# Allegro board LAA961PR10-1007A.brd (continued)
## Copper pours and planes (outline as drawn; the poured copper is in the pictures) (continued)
GND on IN4 (solid shape): 82.12,140 82.29,139.92 82.37,139.75 82.37,134.51 81.88,133.67 82.62,133.05 85.08,133.05 85.08,131.04 81.08,127.04 71.49,127.04 71.16,127.37 71.16,128.8 72.92,128.8 73.65,129.43 73.15,130.26 73.15,137.25 73.37,137.78 73.9,138 74.03,138 79,138 79.66,138.18 80.12,138.69 80.57,139.58 80.68,139.74 81.02,139.96 81.24,140
GND on IN4 (solid shape): 263.02,120.2 246.03,120.2 245.4,120.11 244.82,119.85 241.26,117.59 240.52,117.12 240.33,117.03 240.12,117 235.7,117 234.81,116.64 234.45,115.75 234.45,114.94 234.3,114.49 233.91,114.22 233.78,114.17 233.67,114.1 233.58,114.09 233.51,114.15 233.44,114.33 233.36,114.5 233.55,114.63 233.77,114.71 233.89,114.8 233.94,114.94 233.94,115.75 234.45,117 235.7,117.51 240.12,117.51 240.19,117.52 240.25,117.55 241.1,118.09 244.54,120.28 245.25,120.6 246.03,120.71 263.02,120.71
GND on IN4 (solid shape): outline of 189 points within 234.07,127.91 244.37,138.6
GND on IN4 (solid shape): 266.35,139.25 268,137.6 269.65,139.25 269.65,140 270.18,140 270.57,139.88 270.85,139.58 270.86,139.56 271.43,138.41 271.71,138.11 272.11,138 272.3,138 272.47,137.92 272.55,137.75 272.55,135.45 272.91,134.56 273.8,134.2 282.4,134.2 283.29,134.56 283.65,135.45 283.65,139.25 283.87,139.78 284.4,140 285.43,140 285.6,139.92 285.68,139.75 285.68,131.73 285.3,131.35 285.3,129.18 285.14,129.02 284.4,129.02 281.06,132.36 275.12,132.36 273.8,133.69 272.83,133.98 272.18,134.75 271.25,135.68 260.73,135.68 258.08,133.03 252.66,133.03 252.73,133.21 252.75,133.39 252.75,134.65 252.75,135.82 253.05,136.06 253.15,136.42 253.15,137.47 253.51,137.65 253.65,138.02 253.65,138.35 253.73,138.52 253.9,138.6 254.86,138.6 259.6,138.6 259.6,140.75 259.68,140.92 259.85,141 266.35,141
GND on IN4 (solid shape): 58.4,138.6 58.93,138.38 59.15,137.85 59.15,130.26 58.66,129.42 59.4,128.8 60.51,128.8 61.14,128.8 61.14,128.29 60.54,128.29 58.75,126.49 58.36,126.42 58.28,126.03 54.4,122.14 54.4,120.68 65.44,105.43 66.26,86.61 66.5,86.61 68.66,84.45 66.5,82.29 64.84,82.29 52.78,67.46 34.5,61.89 6.2,61.89 5.68,61.67 5.46,61.15 5.46,54.27 5.29,53.41 4.8,52.67 4.18,52.05 4.02,51.81 3.96,51.53 3.96,45.25 3.45,44 2.2,43.49 1,43.49 0.83,43.42 0.76,43.25 0.76,16.3 0.25,16.3 0.25,43.25 0.47,43.78 1,44 2.2,44 3.09,44.36 3.45,45.25 3.45,51.53 3.55,52.01 3.82,52.41 4.44,53.03 4.82,53.6 4.95,54.27 4.95,61.15 5.32,62.03 6.2,62.4 34.5,62.4 52.62,67.97 64.48,82.76 64.5,82.8 66.5,82.8 68.15,84.45 66.5,86.1 65.73,86.1 65.65,86.14 65.64,86.23 64.09,107.48 49.64,123.13 48.19,124.51 47.65,126.44 47.65,138.35 47.73,138.52 47.9,138.6 58.09,138.6
GND on IN4 (solid shape): outline of 198 points within 0.25,0.25 236.25,109.92
GND on IN4 (solid shape): outline of 1199 points within 95.84,124.76 224.02,140.6
GND on IN4 (solid shape): outline of 2707 points within 56.97,25.32 93.25,34.58
GND on GND1: outline of 314 points within 0.26,0.25 287.14,141 ; 1 cut-out
GND on GND2: outline of 315 points within 0.26,0.25 287.14,141 ; 1 cut-out
GND on VCC: outline of 255 points within 0.25,15.98 190.45,140.6
GND on VCC: 135.05,19.61 132.38,22.28 55.69,22.28 55.69,33.35 57.26,34.92 84.25,34.92 86.62,37.29 86.62,64.97 90.43,68.78 90.43,72.78 93.52,75.87 101.43,75.87 102.26,75.05 103.49,75.05 104.06,75.62 124.21,75.62 124.21,75.58 124.8,74.98 126.71,74.98 127.41,74.29 127.72,74.29 128.15,73.86 128.15,73.81 128.13,73.74 128.15,73.71 128.15,69.16 129.12,68.19 129.95,68.19 131.51,66.62 131.51,63.83 134.71,60.63 137.16,60.63 137.4,60.55 137.65,60.63 143.92,60.63 145.19,59.36 147.79,59.36 148.36,58.79 172.55,58.79 184.16,47.18 185.88,47.18 195.65,37.41 195.65,23.02 194.78,22.15 172.05,22.15 169.51,19.61
GND on GND3: outline of 313 points within 0.26,0.25 287.14,141
GNDA on TOP (solid shape): 217.34,67.23 217.34,67.2 217.4,66.89 217.68,66.75 217.72,66.74 217.73,66.7 217.73,64.54 217.59,64.41 217.39,64.41 217.39,65.3 216.17,66.52 216.17,67.35 217.22,67.35
GNDA on TOP (solid shape): 211.42,67.36 211.83,67.36 214.19,67.36 214.9,66.65 214.9,66 216.12,64.78 216.12,63.96 215.43,63.96 215.41,63.94 214.91,63.94 214.87,63.9 214.63,63.9 214.62,63.91 214.1,63.91 214.07,63.88 214,63.88 213.97,63.91 213.39,63.91 213.3,64 211.34,64 211.29,64.05 210.81,64.05 210.44,63.68 209.87,63.68 209.56,63.37 209.16,63.37 208.99,63.55 208.99,64.24 208.69,64.53 208.69,65.31 208.76,65.37 210.77,65.37 211.06,65.67 212.07,65.67 212.19,65.79 212.19,66.67 212.03,66.83 211.34,66.83 210.44,67.73 210.44,67.97 210.5,68.04 210.75,68.04
GNDA on IN2 (solid shape): outline of 781 points within 206.05,62.96 221.71,76.17
GNDA on GND1, GND2: 207.44,63.05 206.42,64.06 206.1,64.06 205.87,64.29 205.87,66.75 207.05,67.94 208.77,67.94 209.11,68.27 209.11,72.87 208.2,73.78 207.97,73.78 207.97,74.56 208.13,74.73 209.72,74.73 210.19,75.2 210.19,77.04 211.12,77.97 219.67,77.97 219.9,77.74 219.9,75.64 221.81,73.74 221.81,69.76 221.58,69.52 218.97,69.52 217.68,68.23 217.68,64.8 216.88,64 211.03,64 210.08,63.05
GNDA_CHG on TOP (solid shape): 36.07,43.4 39.18,43.4 39.37,43.21 40.52,43.21 40.67,43.06 40.67,42.36 40.38,42.36 40.2,42.18 40.2,41.2 40.04,41.05 40.04,40.52 40.05,40.52 40.24,40.33 40.24,40.31 40.46,40.31 40.59,40.29 40.73,40.31 40.81,40.31 40.95,40.17 40.95,39.41 40.82,39.28 38.34,39.28 37.71,38.65 36.25,38.65 36.1,38.8 36.1,42.26 35.75,42.6 34.72,42.6 34.41,42.92 34.41,43.35 34.94,43.35 34.94,43.83 34.39,43.83 34.39,44.21 34.44,44.26 35.21,44.26
VDD_1.35V on TOP (solid shape): 74.78,20.86 74.78,20.42 74.79,20.41 74.79,19.37 74.54,19.12 73.88,19.12 73.69,19.31 73.69,20.7 74.01,21.02 74.62,21.02
VDD_1.35V on BOTTOM (solid shape): 74.7,20.77 74.7,20.46 74.84,20.32 75.25,20.32 75.42,20.16 75.42,19.42 75.47,19.37 76.56,19.37 76.66,19.27 76.66,18.24 76.58,18.16 74.63,18.16 74.17,18.62 74.17,20.81 74.28,20.92 74.55,20.92
+BL_PWR_SRC on TOP (solid shape): outline of 129 points within 92.44,110.79 99.39,116.73
+BL_PWR_SRC on BOTTOM (solid shape): 98.59,116.78 98.59,115.6 98.99,115.21 99.24,115.21 99.37,115.08 99.37,113.82 99.17,113.62 97.67,113.62 97.51,113.77 97.51,115.13 97.34,115.31 97.34,116.77 97.42,116.86 98.52,116.86
+DC_IN on TOP (solid shape): 69.41,101.4 71.14,101.4 71.24,101.29 71.24,100.57 70.74,100.07 70.74,98.42 70.04,97.72 67.85,97.72 67.69,97.87 67.69,101.59 67.76,101.66 69.15,101.66
+DC_IN on BOTTOM (solid shape): 48.28,41.96 50.32,41.96 50.64,41.65 50.64,40.01 50.14,39.51 48.86,39.51 48.85,39.5 47.98,39.5 47.74,39.74 47.74,41.71 48.01,41.98 48.26,41.98
+DC_IN on BOTTOM (solid shape): outline of 1580 points within 44.06,58.09 75.67,102.03
+DC_IN on IN3 (solid shape): outline of 265 points within 46.17,38.11 51.84,65.54
+DC_IN_SS on TOP (solid shape): 46.36,41.01 46.36,39.11 45.94,38.69 44.14,38.69 43.68,39.15 43.6,39.28 43.47,39.36 43.45,39.39 43.45,41.37 43.56,41.48 45.89,41.48
+DC_IN_SS on BOTTOM (solid shape): outline of 87 points within 43.09,38.73 47.49,47.49
+DCIN on TOP (solid shape): 44.11,45.61 44.11,43.87 43.65,43.41 39.51,43.41 39.31,43.62 39.31,44.1 39.5,44.29 40.07,44.29 40.31,44.3 40.49,44.47 40.5,44.5 40.52,44.54 42.46,44.54 42.85,44.92 42.85,45.54 43.04,45.74 43.98,45.74
+DCIN on BOTTOM (solid shape): 40.69,44.05 40.69,43.56 40.6,43.48 39.26,43.48 39.02,43.23 39.02,42.74 38.98,42.7 38.85,42.7 38.81,42.74 38.81,43.53 39.49,44.2 40.54,44.2
+DCIN_JACK on TOP (solid shape): 82.37,116.92 82.37,116.13 81.75,115.5 81.51,115.5 81.41,115.4 81.4,115.4 81.2,115.3 81.1,115.11 81.1,115.09 80.82,114.81 80.82,113.42 80.66,113.26 79.66,113.26 79.54,113.13 79.54,112.27 79.33,112.06 78.81,112.06 78.54,112.33 78.54,115.09 79.26,115.81 79.26,116.86 79.56,117.15 82.15,117.15
+DCIN_JACK on BOTTOM (solid shape): 82.8,114.32 82.8,111.94 82.42,111.56 74.23,111.56 72.3,109.63 72.26,109.63 72.21,109.62 72.16,109.61 72.12,109.58 72.07,109.55 72.04,109.52 72,109.48 71.98,109.44 71.95,109.38 71.94,109.33 71.94,109.27 71.94,109.22 71.95,109.19 71.95,104.58 71.65,104.28 67.8,104.28 67.44,104.64 67.44,108.16 69.03,108.16 69.03,108.1 69.03,108.05 69.05,108 69.07,107.95 69.1,107.91 69.14,107.87 69.18,107.84 69.23,107.81 69.28,107.79 69.33,107.78 69.38,107.77 69.44,107.78 69.49,107.79 69.54,107.81 69.58,107.84 69.63,107.87 69.66,107.91 69.69,107.95 69.71,108 69.73,108.05 69.74,108.1 69.74,108.16 69.73,108.21 69.71,108.26 69.69,108.31 69.66,108.35 69.63,108.39 69.58,108.43 69.54,108.45 69.49,108.47 69.44,108.48 69.38,108.49 69.33,108.48 69.28,108.47 69.23,108.45 69.18,108.43 69.14,108.39 69.1,108.35 69.07,108.31 69.05,108.26 69.03,108.21 69.03,108.16 67.44,108.16 67.44,113.27 68.77,114.61 82.52,114.61
+DOCK_PWR_BAR on TOP (solid shape): 202.5,24.83 202.5,20.9 202.17,20.58 200,20.58 199.89,20.46 199.89,16.84 199.81,16.77 198.07,16.77 197.93,16.91 197.93,21.11 198.47,21.64 199.49,21.64 199.74,21.89 199.74,25.02 202.3,25.02
+DOCK_PWR_BAR on TOP (solid shape): outline of 159 points within 139.61,130.7 147.54,138.92
+DOCK_PWR_BAR on BOTTOM (solid shape): 202.31,24.78 202.31,17.66 201.31,16.65 201.31,15.78 201.26,15.73 199.44,15.73 199.16,16.01 199.16,21.52 199.66,22.01 199.66,24.86 199.82,25.02 202.07,25.02
+DOCK_PWR_BAR on IN4 (solid shape): outline of 2551 points within 221.8,34.7 233.67,97.17
+DOCK_PWR_BAR on VCC: outline of 102 points within 130.75,17.45 233.67,139.58
+LCDVDD on TOP (solid shape): 78.35,124.93 78.35,122.8 78.06,122.51 75.75,122.51 75.59,122.66 75.59,124.25 76.08,124.73 76.08,125.07 76.24,125.24 78.04,125.24
+LCDVDD on BOTTOM (solid shape): 92.13,116.78 92.13,115.52 92.65,115 93.23,115 93.43,114.81 93.43,114.07 93.3,113.94 92.36,113.94 91.82,114.48 90.86,114.48 90.67,114.67 90.67,115.1 90.97,115.41 90.99,115.41 91.15,115.48 91.22,115.64 91.22,115.66 91.33,115.76 91.33,116.75 91.46,116.88 92.03,116.88
+LCDVDD on IN4 (solid shape): 78.78,125.25 78.78,123.14 78.54,122.9 76.61,122.9 76.27,123.24 76.27,125.2 76.42,125.35 78.68,125.35
+LCDVDD on IN4 (solid shape): 92.48,116.6 92.48,114.93 92.29,114.75 90.82,114.75 90.57,115 90.57,117.05 90.77,117.25 91.82,117.25
+PBATT on TOP (solid shape): 15.39,52.56 15.39,46.38 15.18,46.17 14.21,46.17 13.64,46.74 13.53,47.3 13.03,48.45 12.39,49.3 11.79,49.83 11.03,50.26 10.02,50.66 10.02,52.89 10.43,53.29 14.66,53.29
+PBATT on BOTTOM (solid shape): 13.9,51.07 14.89,51.07 15.31,50.65 15.31,46.19 15.15,46.04 14.28,46.04 13.66,46.66 13.6,46.69 13.52,47.35 13.13,48.26 12.72,48.97 11.95,49.74 11.78,49.84 11.22,50.17 10.73,50.37 10.27,50.54 9.49,50.7 8.98,50.7 8.69,50.99 8.69,52.42 8.97,52.7 12.27,52.7
+PBATT on BOTTOM (solid shape): outline of 264 points within 159.88,6.53 195.01,21.67
+PBATT on IN3 (solid shape): outline of 245 points within 13.32,39.49 32.13,48.61
+PBATT on VCC: 61.58,1.42 61.12,1.58 60.87,2 60.37,4.32 59.58,5.62 58.15,6.12 5.2,6.12 4.68,6.33 4.47,6.85 4.47,9.85 3.81,11.46 2.2,12.12 1.27,12.12 1.27,42.98 2.2,42.98 3.81,43.64 4.47,45.25 4.47,51.53 4.49,51.62 4.54,51.69 5.16,52.31 5.76,53.21 5.97,54.27 5.97,61.15 6.04,61.31 6.2,61.38 16.27,61.38 16.27,46.03 15.26,45.02 15.26,16.62 15.24,16.61 15.24,16.33 18.12,13.45 85.43,13.45 86.26,12.63 163.49,12.63 164.26,13.39 187.16,13.39 187.84,12.71 187.84,6.12 183.11,6.12 183.11,6.12 180.56,6.12 179.7,5.95 178.96,5.46 178.76,5.26 147.8,5.26 147.66,5.33 147.52,5.38 145.84,5.99 145.47,6.09 145.08,6.12 78.57,6.12 77.14,5.62 76.35,4.32 75.85,2 75.6,1.58 75.14,1.42 74.54,1.42 74.37,1.44 74.21,1.5 68.36,2.92 62.51,1.5 62.35,1.44 62.18,1.42
+PCH_VCC1P05 on IN2 (solid shape): outline of 243 points within 127.45,85.02 129.1,89.53
+PCH_VCCDSW on TOP (solid shape): outline of 569 points within 125.76,67.26 128.13,75.44
+PCH_VCCDSW3_3 on TOP (solid shape): outline of 85 points within 132.35,73.78 138.72,75.64
+PCH_VCCDSW3_3 on IN1 (solid shape): 157.62,75.76 157.62,74.59 157.46,74.43 156.43,74.43 156.12,74.73 156.12,76.06 156.32,76.25 157.13,76.25
+PWR_SRC on TOP (solid shape): 92.29,112.76 92.4,112.51 92.64,112.41 92.68,112.38 92.98,112.38 93.15,112.21 93.15,110.9 92.9,110.65 90.35,110.65 89.99,111.02 89.99,112.64 90.37,113.03 92.03,113.03
+PWR_SRC on TOP (solid shape): 28.96,58.56 28.96,56.94 28.18,56.16 28.18,50.23 27.33,49.38 17.67,49.38 17.2,49.85 17.2,51.08 17.22,51.21 17.2,51.34 17.2,52.24 17.24,52.28 25.62,52.28 25.86,52.52 25.86,55.3 25.25,55.91 25.25,58.35 25.77,58.87 28.65,58.87
+PWR_SRC on TOP (solid shape): 92.48,13.14 92.48,12.61 92.51,12.59 93.17,12.59 93.32,12.44 93.32,11.03 93.18,10.89 93.18,9.33 93.06,9.2 87,9.2 86.9,9.3 86.9,12.39 87.11,12.6 91.39,12.6 91.43,12.64 91.43,13.12 91.46,13.15 91.66,13.15 91.68,13.12 91.68,12.64 91.72,12.6 92.2,12.6 92.23,12.63 92.23,13.14 92.26,13.16 92.46,13.16
+PWR_SRC on BOTTOM (solid shape): 78.9,102.14 79.61,102.14 79.61,102.67 80.1,102.67 80.1,102.67 80.1,102.16 80.1,102.16 80.1,102.12 80.81,102.12 81.11,101.82 81.11,98.53 80.77,98.2 77.47,98.2 76.96,98.71 76.96,101.87 77.22,102.13 78.42,102.13 78.43,102.15 78.43,102.67 78.9,102.67
+PWR_SRC on BOTTOM (solid shape): 197.25,69.59 197.25,67.24 197.04,67.03 195.96,67.03 195.81,67.19 195.81,68.14 195.77,68.18 195.29,68.18 195.27,68.2 195.27,68.41 195.29,68.43 195.8,68.43 195.82,68.46 195.82,68.94 195.8,68.96 195.29,68.96 195.27,68.99 195.27,69.22 195.28,69.23 195.8,69.23 195.82,69.26 195.82,69.68 195.85,69.7 197.13,69.7
+PWR_SRC on BOTTOM (solid shape): 37.84,17.05 37.95,17.05 37.96,17.03 37.96,16.36 37.98,16.35 38.5,16.35 38.51,16.34 38.51,15.94 38.47,15.9 37.99,15.9 37.96,15.88 37.96,15.19 37.99,15.17 38.5,15.17 38.51,15.15 38.51,14.71 38.5,14.7 37.98,14.7 37.96,14.68 37.96,12.16 37.63,11.83 33.61,11.83 33.31,12.12 33.31,16.64 33.73,17.06 37.82,17.06
+PWR_SRC on BOTTOM (solid shape): outline of 85 points within 15.57,43.66 25.09,54.82
+PWR_SRC on IN2 (solid shape): outline of 3861 points within 1.81,6.57 94.57,100.6
+PWR_SRC on IN3 (solid shape): 201.04,29.04 201.04,27.02 200.7,26.68 199.51,26.68 199.07,27.12 199.07,28.3 198.48,28.89 198.26,28.89 198.11,29.04 198.11,29.77 198.32,29.98 200.1,29.98
+PWR_SRC on IN3 (solid shape): 95.62,12.68 95.62,10.18 95.39,9.96 87.16,9.96 86.96,10.16 86.96,10.39 93.25,10.39 93.25,10.34 93.25,10.29 93.27,10.24 93.29,10.19 93.32,10.14 93.36,10.1 93.4,10.07 93.45,10.04 93.5,10.03 93.55,10.01 93.6,10.01 93.65,10.01 93.71,10.03 93.76,10.04 93.8,10.07 93.84,10.1 93.88,10.14 93.91,10.19 93.93,10.24 93.95,10.29 93.96,10.34 93.96,10.39 93.95,10.45 93.93,10.5 93.91,10.54 93.88,10.59 93.84,10.63 93.8,10.66 93.76,10.69 93.71,10.71 93.65,10.72 93.6,10.72 93.55,10.72 93.5,10.71 93.45,10.69 93.4,10.66 93.36,10.63 93.32,10.59 93.29,10.54 93.27,10.5 93.25,10.45 93.25,10.39 86.96,10.39 86.96,12.49 87.23,12.76 95.53,12.76
+PWR_SRC on IN4 (solid shape): 197.64,69.49 197.64,65.32 197.37,65.04 195.52,65.04 195.34,65.22 195.34,69.79 195.42,69.86 197.26,69.86
+PWR_SRC on IN4 (solid shape): 200.15,31.74 200.15,29.27 199.78,28.9 198.08,28.9 197.66,29.32 197.66,31.83 197.82,31.99 199.9,31.99
+PWR_SRC on IN4 (solid shape): 80.18,104.39 80.18,98.46 79.86,98.14 77.51,98.14 77.34,98.31 77.34,104.27 77.69,104.63 79.94,104.63
+PWR_SRC on IN4 (solid shape): 92.32,112.91 92.32,112.89 92.29,112.77 92.32,112.64 92.32,108.55 92.04,108.28 90.01,108.28 89.85,108.43 89.85,109.47 88.91,110.4 88.91,112.43 89.54,113.05 92.18,113.05
+PWR_SRC_AC on TOP (solid shape): outline of 356 points within 200.14,11.75 215.27,21.59
+PWR_SRC_AC on BOTTOM (solid shape): 207.26,22.08 207.29,22.07 208.06,22.07 208.08,22.08 211.19,22.08 211.67,21.59 211.67,16.69 211.43,16.45 206.87,16.45 206.8,16.53 206.8,17.97 206.5,18.27 204.68,18.27 204.43,18.51 204.43,21.58 204.93,22.08
+PWR_SRC_AC on BOTTOM (solid shape): 50.64,55.6 50.64,52.06 49.94,51.36 48.85,51.36 48.85,52.73 48.72,53 48.44,53.09 48.16,53 48.03,52.73 48.03,51.36 47.4,51.36 46.89,50.85 46.89,49.39 46.6,49.1 43.92,49.1 43.77,49.25 43.77,54.89 45.04,56.16 50.08,56.16
+PWR_SRC_AC on IN1 (solid shape): 211.13,19.47 211.13,19.04 211.04,18.95 211.04,16.54 210.87,16.37 208.99,16.37 208.73,16.64 208.73,19.26 209.02,19.55 211.05,19.55
+PWR_SRC_AC on IN1 (solid shape): outline of 677 points within 1.34,7.01 19.33,61.08
+PWR_SRC_AC on IN3 (solid shape): outline of 677 points within 6.32,52.31 45.72,61.04
+PWR_SRC_AC on IN4 (solid shape): outline of 3055 points within 1.81,4.87 211.11,61.04
+RTC_CELL on TOP (solid shape): 215.32,86.71 215.83,86.71 215.98,86.56 215.98,86.16 215.76,85.94 215.7,85.91 214.83,85.91 214.69,86.05 214.69,86.62 214.78,86.72 215.32,86.72
+SDC_IN on BOTTOM (solid shape): 48.03,48.97 48.16,48.71 48.44,48.62 48.72,48.71 48.85,48.97 48.85,50.35 49.28,50.35 49.37,50.26 49.37,48.16 50.38,47.15 50.38,44.03 50.24,43.89 46.54,43.89 46.28,44.15 46.28,47.57 47.41,48.7 47.41,50.31 47.45,50.35 48.03,50.35
+SIM_PWR on TOP (solid shape): 70.71,18.28 70.71,15.96 70.59,15.84 70.31,15.84 70.16,15.99 70.16,17.03 69.21,17.98 69.21,18.61 69.25,18.65 70.34,18.65
+SIM_PWR on BOTTOM (solid shape): 213.11,66.44 213.11,64.77 213.27,64.61 213.27,62.4 213.2,62.32 212.83,62.32 212.71,62.44 212.71,63.15 212.73,63.17 212.73,63.68 212.74,63.69 212.74,64.58 212.79,64.63 212.79,64.72 212.81,64.74 212.81,65.74 212.8,65.79 212.79,65.85 212.79,66.42 212.91,66.54 213.01,66.54
+SIM_PWR on IN3 (solid shape): 70.69,18.2 70.69,15.8 70.53,15.64 69.71,15.64 69.47,15.88 69.47,18.32 69.6,18.44 70.45,18.44
+SIM_PWR on IN3 (solid shape): 220.73,43.49 220.73,42.82 219.92,42 219.48,42 219.13,42.36 219.13,43.07 219.85,43.79 220.42,43.79
+SIM_PWR on IN4 (solid shape): 214.11,63.01 214.11,62.41 213.76,62.06 213.26,62.06 212.74,62.57 212.74,63.3 212.82,63.38 213.74,63.38
+SIM_PWR on IN4 (solid shape): 220.69,43.51 220.69,43.17 220.23,42.71 220.06,42.71 219.26,43.51 219.26,43.87 219.65,44.26 219.94,44.26
+USB_RIGHT_PWR on BOTTOM (solid shape): 234.48,126.69 240,126.69 241.26,125.43 241.68,125.43 241.68,125.42 242.12,125.42 242.3,125.25 242.3,123.96 243.04,123.22 245.24,123.22 245.54,123.52 246.83,123.52 246.98,123.37 246.98,121.3 246.91,121.22 242.96,121.22 241.48,122.7 241.48,123.05 241,123.54 241,123.9 239.49,125.4 233.05,125.4 231.9,126.55 231.9,127.44 232.16,127.69 233.48,127.69
+V_DDR_REF on BOTTOM (solid shape): 77.05,15.92 77.05,14.61 76.95,14.51 75.77,14.51 75.2,13.94 74.54,13.94 74.49,13.99 74.49,14.43 74.96,14.9 75.28,14.9 75.28,14.89 76.73,14.89 76.85,15.01 76.85,15.9 76.9,15.95 77.02,15.95
+VCHGR on TOP (solid shape): 18.14,60.53 18.14,54.33 18.09,54.28 12.18,54.28 11.33,55.13 11.33,60.62 11.56,60.85 17.82,60.85
+VCHGR on BOTTOM (solid shape): 18.29,58.72 18.29,52.49 17.41,51.62 17.12,51.62 16.93,51.81 16.93,53.41 16.82,53.52 16.32,53.52 16.09,53.29 16.09,51.96 15.86,51.72 14.28,51.72 12.83,53.18 6.89,53.18 6.45,53.61 6.45,57.76 7.51,58.82 11.28,58.82 11.93,59.46 17.54,59.46
+VDISPLAY_VCC on TOP (solid shape): 252.29,126.72 252.29,125.67 251.48,124.86 250.66,124.86 250.66,124.86 250.64,124.84 250.34,125.14 250.34,125.42 250.65,125.73 250.65,125.81 251.2,126.36 251.2,126.58 251.2,126.63 251.37,126.8 252.21,126.8
+VDISPLAY_VCC on BOTTOM (solid shape): 251.48,129.11 251.48,127.56 252.35,126.69 252.35,125.92 252.12,125.7 251.42,125.7 251.39,125.73 251.39,126.34 251.26,126.46 251.26,126.81 251.04,127.03 251.04,129.11 251.13,129.2 251.39,129.2
+VHDMI_VCC on BOTTOM (solid shape): 96.03,131.02 96.03,129.34 96.86,128.51 97.62,128.51 97.75,128.38 97.75,127.39 97.52,127.16 96.96,127.16 96.62,127.5 96.18,127.5 96.04,127.36 94.84,127.36 94.66,127.54 94.07,127.54 93.75,127.22 93.75,126.86 93.45,126.56 91.57,126.56 91.43,126.7 91.43,127.32 91.57,127.46 92.84,127.46 92.85,127.47 93.01,127.47 93.12,127.57 93.12,127.74 93.47,128.09 94.08,128.71 94.08,131.12 94.26,131.3 95.75,131.3
+VLDOIN_1.35V on TOP (solid shape): 82.07,17.19 82.07,16.96 82.04,16.93 81.54,16.93 81.51,16.91 81.51,16.46 81.52,16.45 82.07,16.45 82.08,16.44 82.08,15.74 81.98,15.64 79.63,15.64 79.42,15.85 79.42,16.45 79.89,16.92 81.14,16.92 81.46,17.24 82.02,17.24
+VLDOIN_1.35V on BOTTOM (solid shape): 79.94,16.36 80.15,16.36 80.27,16.25 80.27,15.84 80.2,15.78 79.9,15.78 79.52,16.16 79.52,16.36 79.36,16.51 78.49,16.51 78.44,16.56 78.44,16.7 78.5,16.77 79.53,16.77
-DCIN_JACK on TOP (solid shape): outline of 91 points within 72.27,104.68 82.8,110.74
-DCIN_JACK on BOTTOM (solid shape): outline of 109 points within 72.27,104.2 82.8,110.59
BOOT_1.35V on BOTTOM (solid shape): 80.11,16.95 81.97,16.95 82.12,16.79 82.12,16.11 82.02,16.01 80.52,16.01 80.41,16.12 80.41,16.59 80.33,16.67 79.92,16.67 79.63,16.96 78.53,16.96 78.45,17.03 78.45,17.1 78.51,17.16 79.9,17.16
BOOT_1.35V_C on BOTTOM (solid shape): 83.05,18.15 83.05,16.03 82.98,15.97 82.41,15.97 82.35,16.03 82.35,18.16 82.39,18.2 83,18.2
BQ24770_REGN on BOTTOM (solid shape): 36.27,46.21 36.27,45.34 36.78,44.84 37.21,44.84 37.51,44.54 37.51,44.46 37.54,44.39 37.54,43.97 37.42,43.84 37.42,42.73 37.38,42.69 37.28,42.69 37.21,42.75 37.21,43.84 36.03,45.03 35.57,45.03 35.36,45.24 35.36,46.21 35.49,46.33 36.15,46.33
BST_3V on TOP (solid shape): 44.12,24.77 45.72,24.77 45.75,24.74 45.75,24.6 45.72,24.58 43.39,24.58 43.27,24.46 42.69,24.46 42.61,24.54 42.61,25.3 42.67,25.36 43.53,25.36
BST_3V_C on TOP (solid shape): 41.94,26.6 41.94,24.51 41.8,24.37 41.25,24.37 41.11,24.51 41.11,25.31 40.67,25.76 40.67,26.62 40.76,26.71 41.82,26.71
BST_5V on TOP (solid shape): 51.32,25.19 51.32,24.31 51.31,24.3 50.59,24.3 50.31,24.58 47.82,24.58 47.74,24.65 47.74,24.68 47.83,24.77 48.64,24.77 48.71,24.83 50.1,24.83 50.49,25.21 51.3,25.21
BST_5V_C on TOP (solid shape): 52.8,26.38 52.8,24.39 52.69,24.29 52.14,24.29 52.06,24.36 52.06,26.43 52.11,26.48 52.69,26.48
BST_+V1.05SP on TOP (solid shape): 192.38,67.64 192.38,66.42 192.17,66.21 191.2,66.21 191.02,66.39 191.02,67.64 191.18,67.8 192.23,67.8
BST_+V1.05SP_C on TOP (solid shape): 192.13,69.19 192.13,68.06 192,67.94 189.99,67.94 189.69,68.24 189.69,69.12 189.83,69.26 192.06,69.26
CHAGER_SRC on TOP (solid shape): outline of 89 points within 31.98,46.07 42.31,56.44
CHAGER_SRC on BOTTOM (solid shape): 43.06,55.86 43.06,52.28 43.14,52.19 43.61,52.19 43.61,51.65 43.06,51.65 43.06,50.89 43.61,50.89 43.61,50.46 43.06,50.46 43.06,49.71 43.61,49.71 43.61,48.05 42.99,47.44 42.99,47.16 42.85,47.02 40.43,47.02 40.29,47.16 40.29,47.68 40.12,47.85 37.37,47.85 37.07,47.56 37.07,46.95 36.91,46.78 34.06,46.78 33.92,46.92 33.92,48.58 34.35,49.01 38.24,49.01 39,49.77 39,55.65 39.48,56.12 42.79,56.12
CHAGER_SRC on IN1 (solid shape): 37.39,48.7 37.39,47.15 37.14,46.89 34.2,46.89 33.82,47.27 33.82,48.64 34.04,48.86 37.23,48.86
CHAGER_SRC on IN1 (solid shape): 42.83,55.32 42.83,52.23 42.57,51.97 39.91,51.97 39.73,52.14 39.73,55.34 40.1,55.71 42.45,55.71
CHAGER_SRC on IN2 (solid shape): 37.14,48.62 37.14,47.08 36.98,46.93 34.19,46.93 33.96,47.16 33.96,48.68 34.13,48.85 36.91,48.85
CHAGER_SRC on IN2 (solid shape): 42.67,55.43 42.67,52.29 42.37,51.98 39.89,51.98 39.75,52.12 39.75,55.34 40.07,55.65 42.45,55.65
CHAGER_SRC on IN4 (solid shape): 37.23,48.62 37.23,47.18 36.96,46.92 34.24,46.92 34.04,47.12 34.04,48.64 34.25,48.86 36.98,48.86
CHAGER_SRC on IN4 (solid shape): 42.71,55.36 42.71,52.2 42.5,51.98 40.13,51.98 39.75,52.37 39.75,55.31 40.08,55.64 42.43,55.64
CHG_BTS on BOTTOM (solid shape): 37.48,46.04 37.48,45.36 37.91,44.93 37.91,43.83 37.87,43.79 37.82,43.74 37.82,42.8 37.75,42.73 37.67,42.73 37.61,42.79 37.61,43.84 37.63,43.87 37.63,43.88 37.67,43.92 37.67,44.05 37.67,44.1 37.67,44.59 37.24,45.03 36.86,45.03 36.45,45.43 36.45,46.23 36.57,46.35 37.18,46.35
CHG_BTS_C on BOTTOM (solid shape): 39.8,46.42 39.8,45.74 39.68,45.61 38.8,45.61 38.45,45.25 37.89,45.25 37.84,45.3 37.84,46.36 38.04,46.56 39.66,46.56
CHG_LGATE on BOTTOM (solid shape): 37.02,43.84 37.02,42.74 36.98,42.7 36.85,42.7 36.81,42.74 36.81,43.54 36.63,43.72 36.09,43.72 35.77,44.05 35.77,44.52 35.93,44.68 36.18,44.68
CHG_LGATE on BOTTOM (solid shape): 38.84,54.35 38.84,52.54 38.75,52.45 37.35,52.45 37.25,52.55 37.25,53.98 37.7,54.44 37.99,54.44 37.99,54.44 38.76,54.44
CHG_LGATE on IN3 (solid shape): 36.89,45.63 36.89,43.95 36.67,43.73 36.35,43.73 35.64,44.44 35.64,45.55 35.83,45.74 36.77,45.74
CHG_LGATE on IN3 (solid shape): 38.96,54.18 38.96,52.42 38.85,52.31 38.84,52.31 38.5,51.97 37.62,51.97 37.24,52.35 37.24,52.96 37.84,53.56 37.84,54.21 38.07,54.44 38.7,54.44
CHG_SNUB on TOP (solid shape): 31.31,55.3 31.31,53.37 31.12,53.18 28.65,53.18 28.5,53.33 28.5,54.04 28.74,54.28 29.58,54.28 29.94,54.64 29.94,55.15 30.18,55.39 31.22,55.39
CHG_SW on TOP (solid shape): 33.87,55.32 33.87,52.64 33.56,52.33 31.85,52.33 31.77,52.42 31.77,55.3 32.01,55.54 33.66,55.54
CHG_SW on BOTTOM (solid shape): 39.67,45.47 40.35,45.47 40.45,45.37 40.45,44.38 40.41,44.34 39.44,44.34 38.62,43.53 38.62,42.75 38.57,42.7 38.46,42.7 38.41,42.75 38.41,43.72 38.81,44.12 38.81,45.33 38.95,45.47 39.67,45.47
CHG_SW on BOTTOM (solid shape): 33.18,54.41 33.18,52.45 33.49,52.14 38.59,52.14 38.79,51.95 38.79,49.86 38.17,49.24 33.8,49.24 32.54,47.98 32.54,44.74 32.29,44.49 27.55,44.49 27.1,44.94 27.1,53.79 27.88,54.56 33.04,54.56
CHG_SW on IN4 (solid shape): 41.23,49.15 41.23,46.73 41.22,46.7 41.21,46.65 41.21,46.6 41.22,46.55 41.23,46.52 41.23,45.16 41.21,45.13 41.19,45.09 41.17,45.04 41.15,44.99 41.15,44.93 41.15,44.88 41.16,44.83 41.18,44.78 41.21,44.72 40.86,44.37 39.97,44.37 39.79,44.54 39.79,45.98 40.07,46.26 40.07,48.15 39.28,48.94 39.74,48.94 39.74,48.88 39.75,48.83 39.76,48.78 39.79,48.73 39.82,48.69 39.85,48.65 39.9,48.62 39.94,48.59 39.99,48.57 40.04,48.56 40.1,48.55 40.15,48.56 40.2,48.57 40.25,48.59 40.3,48.62 40.34,48.65 40.38,48.69 40.41,48.73 40.43,48.78 40.44,48.83 40.45,48.88 40.45,48.94 40.44,48.99 40.43,49.04 40.41,49.09 40.38,49.13 40.34,49.17 40.3,49.21 40.25,49.23 40.2,49.25 40.15,49.26 40.1,49.27 40.04,49.26 39.99,49.25 39.94,49.23 39.9,49.21 39.85,49.17 39.82,49.13 39.79,49.09 39.76,49.04 39.75,48.99 39.74,48.94 39.28,48.94 38.66,49.56 37.98,49.56 37.8,49.74 37.8,50.89 38.03,51.12 39.26,51.12
CHG_UGATE on BOTTOM (solid shape): 39.81,47.64 39.81,46.85 39.68,46.72 37.42,46.72 37.25,46.9 37.25,47.52 37.44,47.72 39.73,47.72
CHG_UGATE on BOTTOM (solid shape): 38.65,44.99 38.65,44.14 38.28,43.77 38.28,43.72 38.22,43.65 38.22,42.76 38.17,42.71 38.06,42.71 38,42.78 38,43.74 38.05,43.79 38.05,44.44 38.07,44.53 38.05,44.62 38.05,45.01 38.15,45.11 38.52,45.11
CHG_UGATE on IN4 (solid shape): 39.82,47.43 39.82,46.49 39.28,45.95 39.28,43.96 39.07,43.74 38.09,43.74 38,43.83 38,46.99 38.63,47.62 39.41,47.62 39.41,47.62 39.62,47.62
CORE_BOOT on BOTTOM (solid shape): 95.44,112.26 95.44,112.06 95.23,111.85 95.23,111.72 95.23,111.59 95.35,111.47 96.26,111.47 96.28,111.45 96.28,111.24 96.19,111.16 95.02,111.16 94.93,111.25 94.93,111.82 94.81,111.94 94.75,111.94 94.63,112.07 94.01,112.07 93.94,112.14 93.94,112.74 94.02,112.82 94.89,112.82
CORE_BOOT_C on BOTTOM (solid shape): 93.77,112.69 93.77,110.89 93.7,110.81 92.79,110.81 92.7,110.9 92.7,112.03 93.04,112.37 93.04,112.67 93.14,112.77 93.7,112.77
CORE_BOOT_R on BOTTOM (solid shape): 94.8,111.76 94.8,111.1 94.88,111.03 96.21,111.03 96.27,110.97 96.27,110.84 96.23,110.8 94.11,110.8 94.03,110.87 94.03,111.74 94.11,111.81 94.75,111.81
CORE_SNUB on TOP (solid shape): 103.25,108.7 103.25,107.81 103.13,107.69 102.56,107.69 102.46,107.58 102.46,106.58 102.33,106.45 101.57,106.45 101.43,106.6 101.43,108.78 101.48,108.83 103.13,108.83
CORE_SW on TOP (solid shape): 103.25,112.07 103.25,110.61 102.99,110.36 101.47,110.36 101.28,110.55 101.28,112.07 101.41,112.2 103.12,112.2
CORE_SW on BOTTOM (solid shape): 104.16,111.62 105.86,111.62 106.3,111.18 106.3,109.4 106.09,109.19 103.85,109.19 103.76,109.1 103.76,108.44 103.83,108.37 106.15,108.37 106.26,108.26 106.26,107.32 106,107.05 102.12,107.05 101.32,107.85 99.13,107.85 98.87,108.11 98.87,110.63 98.91,110.67 100.94,110.67 100.94,110.68 101.34,111.08 101.34,112.03 101.51,112.21 103.57,112.21
DH_1.35V on TOP (solid shape): 84.22,19.51 84.22,18.6 84.14,18.52 82.17,18.52 80.74,17.08 79.71,17.08 79.47,17.33 79.47,17.67 81.43,19.64 84.09,19.64
DH_1.35V on BOTTOM (solid shape): 80.7,17.68 80.7,17.24 80.62,17.16 80.32,17.16 80.16,17.31 79.78,17.31 79.73,17.36 78.53,17.36 78.49,17.4 78.49,17.52 78.54,17.57 79.57,17.57 79.78,17.78 80.6,17.78
DL_1.35V on TOP (solid shape): 92.33,21.71 92.33,20.89 92.2,20.77 90.25,20.77 90.1,20.92 90.1,21.73 90.17,21.81 92.23,21.81
DL_1.35V on BOTTOM (solid shape): 78.88,19.37 78.88,18.44 78.81,18.37 78.36,18.37 78.21,18.22 78.11,18.22 78.09,18.2 78.04,18.25 78.04,18.99 78.5,19.45 78.81,19.45
DL_1.35V on IN3 (solid shape): 79.21,20.36 79.21,18.66 78.91,18.35 78.36,18.35 78.3,18.41 78.3,20.43 78.4,20.53 79.05,20.53
DL_1.35V on IN3 (solid shape): 92.33,21.76 92.33,20.87 92.18,20.72 90.39,20.72 90.27,20.83 90.27,21.8 90.4,21.92 92.17,21.92
EN_+V1.05SP on BOTTOM (solid shape): 189.03,66.78 189.03,65.84 189.04,65.83 189.04,65.03 188.41,64.4 188.41,63.9 188.25,63.74 185.99,63.74 185.85,63.88 185.85,64.42 186.01,64.57 187.54,64.57 188.64,65.68 188.64,66.52 188.72,66.6 188.72,66.83 188.75,66.86 188.95,66.86
FB_+V1.05SP on BOTTOM (solid shape): 190.38,66.78 190.38,66.01 191.21,65.17 191.9,65.17 193.02,65.17 193.22,64.97 193.56,64.87 193.84,65.09 193.84,65.1 194.22,65.48 194.55,65.48 194.66,65.38 194.66,64.05 194.59,63.99 192.26,63.99 192.15,64.09 192.15,64.77 192.01,64.92 191.02,64.92 190.1,65.84 190.1,66.75 190.19,66.84 190.31,66.84
ILMT_1.05V on BOTTOM (solid shape): 189.92,66.77 189.92,65.83 190.95,64.79 191.87,64.79 191.91,64.75 191.91,64.06 191.85,64 190.45,64 190.38,64.07 190.38,64.82 189.65,65.55 189.65,66.77 189.73,66.84 189.84,66.84
INT_SPK_L+ on TOP (solid shape): 219.93,9.22 219.93,8.12 219.72,7.91 218.21,7.91 218.02,8.1 218.02,9.31 218.05,9.34 219.81,9.34
INT_SPK_L+ on TOP (solid shape): 207.12,76.84 207.12,75.98 207.28,75.81 207.28,74.85 207.12,74.7 207.02,74.7 206.73,74.41 206.73,73.82 206.74,73.72 206.78,73.63 206.78,73.42 206.73,73.37 206.63,73.37 206.58,73.42 206.58,74.49 206.68,74.59 206.72,74.63 206.81,74.73 206.82,74.75 206.82,75.78 206.82,75.78 206.82,75.91 206.58,76.15 206.53,76.15 206.26,76.41 206.26,76.85 206.34,76.93 207.03,76.93
INT_SPK_L+ on IN4 (solid shape): 220.13,8.69 220.13,7.69 220.07,7.62 218.25,7.62 217.85,8.03 217.85,8.54 218.15,8.84 219.98,8.84
INT_SPK_L+ on IN4 (solid shape): 207.2,75.72 207.28,75.68 207.3,75.6 207.47,75.21 207.9,75.27 208.39,75.27 208.61,75.04 208.61,74.25 208.34,73.97 207.91,73.97 207.51,74.37 207.32,74.51 207.08,74.58 207.07,74.59 207,74.65 207,74.65 206.84,74.81 206.84,75.6 206.96,75.72
INT_SPK_L- on TOP (solid shape): 219.97,10.76 219.97,9.7 219.87,9.59 218.05,9.59 217.91,9.74 217.91,10.75 218.01,10.85 219.88,10.85
INT_SPK_L- on TOP (solid shape): 206.11,76.91 206.11,76.57 206.11,76.57 206.11,76.36 206.45,76.02 206.52,76.02 206.69,75.85 206.69,74.79 206.69,74.78 206.38,74.48 206.38,73.42 206.34,73.37 206.23,73.37 206.18,73.43 206.18,74.61 206.24,74.67 206.24,75.64 206.24,75.7 205.94,76 205.91,76 205.59,76.32 205.5,76.32 205.45,76.36 205.45,76.9 205.53,76.98 206.04,76.98
INT_SPK_L- on IN4 (solid shape): 220.26,10.34 220.26,9.39 220.17,9.3 217.97,9.3 217.74,9.53 217.74,9.88 218.4,10.54 220.06,10.54
INT_SPK_L- on IN4 (solid shape): 206.7,75.58 206.69,75.46 206.7,75.42 206.7,74.98 206.69,74.88 206.7,74.78 206.71,74.76 206.72,74.75 206.8,74.63 206.92,74.55 206.93,74.54 207.46,74.01 207.46,73.84 206.99,73.37 206.67,73.37 206.34,73.7 206.34,74.44 206.24,74.53 206.24,75.59 206.35,75.7 206.58,75.7
INT_SPK_R+ on TOP (solid shape): 219.99,13.99 219.99,12.79 219.88,12.68 218.06,12.68 217.96,12.78 217.96,13.91 218.16,14.11 219.88,14.11
INT_SPK_R+ on TOP (solid shape): 204.43,76.79 204.43,76.01 204.74,75.69 205.37,75.69 205.53,75.54 205.53,74.59 205.58,74.53 205.58,73.41 205.54,73.37 205.43,73.37 205.38,73.42 205.38,74.44 205.01,74.81 205.01,75.01 204.54,75.47 204.47,75.58 204.36,75.65 204.33,75.68 204.2,75.68 204.04,75.68 203.6,76.12 203.6,76.83 203.75,76.98 204.24,76.98
INT_SPK_R+ on IN4 (solid shape): 219.09,13.72 219.09,13.49 218.63,13.03 216.78,13.03 216.61,13.2 216.61,14.07 216.72,14.18 218.63,14.18
INT_SPK_R+ on IN4 (solid shape): 205.5,75.6 205.5,73.93 205.42,73.86 205.41,73.85 205.1,73.69 204.89,73.4 204.3,73.4 204.21,73.49 204.21,74.34 204.22,74.37 204.25,74.39 204.5,74.51 204.59,74.76 204.59,74.81 204.58,74.87 204.59,74.9 204.61,74.94 204.68,75.01 204.68,75.54 204.88,75.75 205.35,75.75
INT_SPK_R- on TOP (solid shape): 219.96,12.31 219.96,12.14 219.97,12.13 219.97,11.23 219.88,11.14 218.13,11.14 217.95,11.32 217.95,12.28 218.05,12.39 219.89,12.39
INT_SPK_R- on TOP (solid shape): 205.28,76.81 205.28,76.37 205.29,76.36 205.29,76.3 205.44,76.15 205.56,76.15 206.11,75.61 206.11,74.75 205.98,74.62 205.98,73.41 205.95,73.37 205.82,73.37 205.78,73.41 205.78,74.6 205.65,74.72 205.65,75.62 205.41,75.86 204.76,75.86 204.58,76.04 204.58,76.84 204.62,76.88 205.22,76.88
INT_SPK_R- on IN4 (solid shape): 220.44,12.44 220.44,11.93 220.07,11.56 217.99,11.56 217.66,11.88 217.66,12.43 217.92,12.68 220.19,12.68
INT_SPK_R- on IN4 (solid shape): 206.12,75.66 206.12,75.54 206.11,75.46 206.12,75.39 206.12,74.96 206.11,74.88 206.12,74.8 206.12,74.24 206.16,74.2 206.16,72.85 205.77,72.46 205.31,72.46 205.04,72.72 205.04,73.28 205.65,73.89 205.65,75.63 205.77,75.75 206.03,75.75
INT_SPKR_L+ on TOP (solid shape): 230.55,9.78 230.55,8.77 227.97,6.19 220.86,6.19 220.26,6.79 220.26,9.16 220.35,9.25 221.1,9.25 221.24,9.11 221.24,7.99 221.88,7.34 223.81,7.34 224.32,7.85 227.65,7.85 229.77,9.97 230.36,9.97
INT_SPKR_L- on TOP (solid shape): 231.8,10.24 231.8,9.01 231.68,8.88 230.95,8.88 230.85,8.98 230.85,9.86 230.43,10.28 229.47,10.28 227.87,8.68 224.2,8.68 223.75,9.12 221.92,9.12 221.53,9.52 220.31,9.52 220.23,9.6 220.23,10.78 220.29,10.84 221.62,10.84 222.2,10.26 226.62,10.26 227.48,11.13 230.91,11.13
INT_SPKR_R+ on TOP (solid shape): 232.91,9.78 232.91,7.99 232.78,7.86 232.26,7.86 232.18,7.94 232.18,9.85 232.31,9.97 232.72,9.97
INT_SPKR_R+ on TOP (solid shape): 224.75,13.81 224.75,13.16 224.59,13 224.11,13 223.78,12.67 220.45,12.67 220.33,12.79 220.33,13.79 220.46,13.92 224.64,13.92
INT_SPKR_R+ on IN4 (solid shape): 226.1,13.88 226.1,12.83 225.94,12.67 223.69,12.67 223.57,12.78 223.57,13.94 223.74,14.1 225.88,14.1
INT_SPKR_R+ on IN4 (solid shape): 232.96,8.93 232.96,8.11 232.73,7.88 230.86,7.88 230.54,8.2 230.54,8.84 231.05,9.35 232.54,9.35
INT_SPKR_R- on TOP (solid shape): 234.21,9.92 234.21,8.06 234.03,7.88 233.48,7.88 233.31,8.04 233.31,9.77 233.57,10.02 234.1,10.02
INT_SPKR_R- on TOP (solid shape): 223.92,11.62 224.65,11.62 224.73,11.55 224.73,10.8 224.56,10.63 222.3,10.63 221.83,11.1 220.46,11.1 220.3,11.27 220.3,12.21 220.44,12.35 223.19,12.35
INT_SPKR_R- on IN4 (solid shape): 226.02,11.51 226.02,10.82 225.63,10.43 223.98,10.43 223.64,10.77 223.64,11.56 223.83,11.75 225.78,11.75
INT_SPKR_R- on IN4 (solid shape): 234.44,8.86 234.44,7.05 233.76,6.37 233.36,6.37 233.07,6.66 233.07,7.66 233.5,8.1 233.5,8.94 233.74,9.17 234.13,9.17
LG_3V on TOP (solid shape): 46.05,24.06 46.05,23.14 45.54,22.63 45,22.63 44.74,22.38 44.74,21.73 44.57,21.56 43.07,21.56 42.97,21.66 42.97,22.28 43.09,22.41 44.12,22.41 44.82,23.1 45.56,23.1 45.84,23.38 45.84,24.06 45.87,24.1 46.01,24.1
LG_5V on TOP (solid shape): 48.53,23.84 48.53,22.65 48.45,22.57 47.87,22.57 47.45,22.99 47.45,23.94 47.48,23.97 47.48,23.98 48.39,23.98
LG_5V on TOP (solid shape): 48.57,18.24 48.57,17.81 48.4,17.64 47.75,17.64 47.21,17.1 46.89,17.1 46.68,17.31 46.68,18.19 46.88,18.39 48.41,18.39
LG_5V on IN1 (solid shape): 49.01,18.33 49.01,17.3 48.92,17.21 46.9,17.21 46.74,17.38 46.74,18.15 46.94,18.35 48.99,18.35
LG_5V on IN1 (solid shape): 48.35,23.89 48.35,23.14 48.78,22.72 48.78,22.25 48.85,22.18 48.85,20.91 48.55,20.62 47.86,20.62 47.77,20.7 47.77,22.1 47.88,22.22 47.88,22.81 47.69,23 47.69,23.83 47.83,23.97 48.28,23.97
NB_PSID on BOTTOM (solid shape): 82.82,117.09 82.82,115.41 82.46,115.05 81.83,115.05 81.82,115.09 81.47,115.38 81.12,115.09 81.12,115.05 78.38,115.05 77.98,115.45 77.98,117.01 78.3,117.33 82.59,117.33
PBAT_PRES#_C on BOTTOM (solid shape): 161.39,3.7 161.39,1.76 161.03,1.4 159.87,1.4 159.6,1.67 159.6,3.69 159.89,3.99 161.1,3.99
PBAT_SMBCLK_C on BOTTOM (solid shape): 165.4,2.95 165.4,1.75 165.04,1.39 163.88,1.39 163.61,1.66 163.61,3.68 163.81,3.88 164.46,3.88 164.46,3.89
PBAT_SMBDAT_C on BOTTOM (solid shape): 163.39,3.69 163.39,1.75 163.03,1.39 161.87,1.39 161.6,1.66 161.6,3.68 161.9,3.98 163.11,3.98
PBATT+_C on TOP (solid shape): 157.23,13.35 162.18,13.35 163.54,11.99 168.65,11.99 169.88,10.76 169.88,1.72 169.43,1.27 165.93,1.27 165.57,1.63 165.57,3.47 165.31,3.74 156.85,3.74 155.87,4.72 155.87,10.66 156.17,10.96 156.17,12.82 156.72,13.38 157.2,13.38
PBATT+_C on BOTTOM (solid shape): 159.39,17 159.39,9.33 160.45,8.26 168.56,8.26 169.7,7.12 169.7,1.71 169.38,1.39 165.92,1.39 165.59,1.72 165.59,3.28 164.75,4.12 160.05,4.12 160.05,4.12 156.71,4.12 156.7,4.11 156.24,4.11 156.01,4.33 156.01,14.95 154.94,16.02 154.94,17.24 155.2,17.49 158.89,17.49
PWM1 on BOTTOM (solid shape): 96.19,112.94 96.19,112.23 96.27,112.15 96.27,111.65 96.22,111.59 95.41,111.59 95.36,111.64 95.36,111.8 95.57,112.01 95.57,112.95 95.7,113.08 96.05,113.08
PWR_SRC_ON on TOP (solid shape): 93.17,114.45 93.17,113.53 93.16,113.53 93.16,113.33 92.98,113.15 92.19,113.15 92.12,113.22 91.04,113.22 90.65,113.62 86.91,113.62 86.69,113.83 86.69,114.39 86.86,114.56 92.25,114.56 92.38,114.68 92.93,114.68
REGCTL_PNP10 on BOTTOM (solid shape): 210.7,112.07 210.7,111.31 210.57,111.18 209.88,111.18 209.73,111.03 208.63,111.03 208.5,111.15 208.24,111.15 207.98,111.41 207.98,111.89 208.28,112.2 210.57,112.2
RING2 on TOP (solid shape): 219.42,71.37 221.17,71.37 221.26,71.29 221.26,70.18 221.25,70.18 221.09,70.03 220.23,70.03 219.8,70.46 219.05,70.46 218.47,71.03 217.49,71.03 217.34,71.19 217.34,72.24 217.49,72.39 218.4,72.39
RING2 on TOP (solid shape): 210.32,69.88 210.46,69.74 210.58,69.74 210.62,69.73 210.7,69.67 210.76,69.58 210.77,69.54 210.99,69.33 211.05,69.33 211.19,69.19 211.91,69.19 211.95,69.15 211.95,68.58 211.94,68.57 211.16,68.57 210.13,69.6 210.12,69.6 210.06,69.66 209.15,69.66 209.08,69.73 209.08,69.82 209.16,69.89 210.3,69.89
RING2 on IN1 (solid shape): 210.68,69.74 210.71,69.71 210.71,69.61 210.8,69.52 210.8,69.38 210.85,69.33 212.5,69.33 212.63,69.21 212.63,68.7 212.12,68.19 210.12,68.19 210.02,68.29 210.02,69.62 210.14,69.74 210.34,69.74
RING2 on IN1 (solid shape): 218.46,72.08 218.46,71.22 218.27,71.04 218.24,71.05 218.18,71.06 218.11,71.06 217.84,71.06 217.56,70.78 216.74,70.78 216.41,71.11 215.31,71.11 215.04,71.38 215.04,71.96 215.31,72.23 218.3,72.23
S5_1.35V on BOTTOM (solid shape): 73.57,19.27 73.57,18.3 73.56,18.29 73.56,18.2 74.6,17.16 76.2,17.16 76.25,17.11 76.25,17.01 76.2,16.96 74.44,16.96 73.71,17.68 73.04,17.68 72.9,17.82 72.9,19.28 72.98,19.36 73.48,19.36
SLEEVE on TOP (solid shape): 210.97,70.06 211,70.03 211.97,70.03 211.97,69.47 211.95,69.46 211.04,69.46 210.88,69.61 210.88,69.63 210.79,69.76 210.66,69.85 210.65,69.85 210.63,69.87 210.51,69.87 210.37,70 210.37,70 210.3,70.07 209.12,70.07 209.08,70.11 209.08,70.22 209.15,70.29 210.17,70.29 210.23,70.34 210.69,70.34
SLEEVE on TOP (solid shape): 219.79,76.1 219.79,75.97 219.78,75.96 219.67,75.77 219.64,75.56 219.64,75.36 219.49,75.22 219.31,74.76 219.5,74.31 219.5,73.3 219.91,72.89 221.64,72.89 221.74,72.79 221.74,72.62 221.75,72.61 221.75,71.69 221.6,71.55 219.56,71.55 218.38,72.72 217.86,72.72 217.06,73.52 217.06,74.16 217.36,74.46 218.61,74.46 219.02,74.87 219.02,76.11 219.13,76.11 219.22,76.2 219.69,76.2
SLEEVE on IN1 (solid shape): 218.3,74.44 218.3,73.75 217.92,73.37 216.22,73.37 216.22,74.57 216.39,74.74 218.01,74.74
SLEEVE on IN1 (solid shape): 211.55,71.53 211.55,70.96 211.52,70.93 211.52,69.73 211.32,69.52 210.97,69.52 210.88,69.61 210.86,69.66 210.84,69.71 210.84,69.84 210.81,69.87 210.39,69.87 210.3,69.95 210.3,71.42 210.56,71.67 211.41,71.67
SNB_1.05V on TOP (solid shape): 186.63,70.83 186.63,69.97 186.49,69.83 185.35,69.83 184.98,69.46 184.98,68.01 184.74,67.77 183.33,67.77 183.12,67.97 183.12,70.79 183.33,71 186.46,71
SNUB_1.35V on BOTTOM (solid shape): 85.56,15.4 85.56,14.62 85.38,14.44 84.43,14.44 84.2,14.21 84.2,13.2 84,13 83.04,13 82.87,13.16 82.87,15.13 83.31,15.57 85.38,15.57
SNUB_3V on TOP (solid shape): 40.87,25.02 40.87,23.92 41.14,23.65 41.86,23.65 41.93,23.59 41.94,23.59 41.94,22.75 41.85,22.66 40.45,22.66 39.7,23.41 39.7,24.95 39.82,25.06 40.83,25.06
SNUB_5V on BOTTOM (solid shape): 50.14,21.63 50.14,19.99 49.98,19.83 48.17,19.83 48.03,19.97 48.03,21.58 48.21,21.76 50.02,21.76
SW1 on TOP (solid shape): 53.47,20.11 53.47,16.08 53.27,15.88 51.73,15.88 51.63,15.98 51.63,17.61 51.32,17.91 49.22,17.91 49.13,18 49.13,20.21 49.28,20.36 53.22,20.36
SW1 on TOP (solid shape): 51.32,26.43 51.32,25.59 51.3,25.57 50.57,25.57 49.98,24.97 47.81,24.97 47.73,25.05 47.73,25.11 47.79,25.17 49.15,25.17 49.93,25.95 49.93,26.25 50.14,26.47 51.29,26.47
SW1 on BOTTOM (solid shape): outline of 85 points within 47.46,14.16 53.37,21.73
SW1 on IN1 (solid shape): 51.2,26.25 51.2,25.31 51.08,25.2 49.58,25.2 49.39,25.39 49.39,26.29 49.52,26.42 51.03,26.42
SW1 on IN1 (solid shape): 52.79,20.78 52.79,19.52 52.71,19.45 51.63,19.45 51.48,19.6 51.48,20.64 51.69,20.84 52.73,20.84
SW2 on TOP (solid shape): 39.28,24.51 39.28,23.51 40.71,22.09 42.24,22.09 42.45,21.89 42.45,19.6 42.22,19.37 37.85,19.37 37.57,19.65 37.57,21.02 37.07,21.52 37.07,24.9 37.24,25.06 38.74,25.06
SW2 on TOP (solid shape): 43.49,26.7 43.49,26.15 43.7,25.94 43.75,25.88 43.81,25.83 44.47,25.17 45.7,25.17 45.75,25.12 45.75,25.01 45.7,24.96 44.14,24.96 43.5,25.59 42.17,25.59 42.08,25.68 42.08,26.75 42.22,26.89 43.3,26.89
SW2 on BOTTOM (solid shape): 38.85,23.77 43.3,23.77 43.43,23.63 43.43,20.05 42.32,18.94 38.24,18.94 37.56,19.62 37.56,23.52 37.81,23.78 38.84,23.78
SW2 on IN1 (solid shape): 43.62,26.5 43.62,25.71 43.6,25.71 43.45,25.55 41.84,25.55 41.78,25.61 41.78,26.57 41.97,26.76 43.36,26.76
SW2 on IN1 (solid shape): 39.26,24.39 39.26,22.55 39.18,22.47 37.63,22.47 37.48,22.62 37.48,24.06 37.92,24.5 39.14,24.5
SW_1.35V on TOP (solid shape): 89.44,21.47 89.44,16.84 89.16,16.56 86.65,16.56 86.38,16.84 86.38,18.1 86.05,18.43 84.57,18.43 84.43,18.57 84.43,18.67 84.44,18.69 84.44,19.62 84.31,19.76 83.66,19.76 83.35,20.07 83.35,20.25 83.37,20.26 83.37,21.61 83.48,21.72 89.18,21.72
SW_1.35V on BOTTOM (solid shape): 89.73,20.01 89.73,14.09 89.54,13.9 86.05,13.9 85.77,14.18 85.77,15.68 85.61,15.83 83.59,15.83 83.38,16.04 83.38,16.37 83.39,16.39 83.39,18.06 83.37,18.06 83.12,18.3 83.12,18.32 83.11,18.32 83.01,18.42 82.3,18.42 82.07,18.19 82.07,17.33 82.02,17.28 80.95,17.28 80.89,17.34 80.89,17.85 80.76,17.97 79.76,17.97 79.54,17.76 78.5,17.76 78.45,17.81 78.45,17.91 78.53,17.99 79.44,17.99 79.64,18.19 79.64,18.77 81.31,20.44 89.3,20.44
SW_+V1.05SP on TOP (solid shape): 189.42,69.22 189.42,67.77 189.23,67.58 185.37,67.58 185.19,67.76 185.19,69.12 185.55,69.47 189.17,69.47
SW_+V1.05SP on BOTTOM (solid shape): 187.92,70.96 187.92,68.96 188.08,68.81 189.35,68.81 189.44,68.72 189.44,67.54 189.4,67.5 188.2,67.5 188.13,67.43 188.13,66.41 187.54,65.83 184.81,65.83 184.58,66.06 184.58,71.19 184.74,71.34 187.54,71.34
UG_3V on TOP (solid shape): 37.32,20.59 37.32,19.84 37.12,19.65 36.91,19.65 36.82,19.56 36.82,19.02 36.62,18.81 36.35,18.81 36.24,18.93 36.24,20.59 36.31,20.67 36.31,20.68 37.23,20.68
UG_3V on TOP (solid shape): 44.64,24.38 45.73,24.38 45.76,24.35 45.76,24.21 45.72,24.17 44.72,24.17 44.53,23.98 43.63,23.98 43.55,24.06 43.55,24.39 43.61,24.45 44.57,24.45
UG_3V on IN1 (solid shape): 38.01,19.85 38.01,18.84 37.76,18.58 36.43,18.58 36.24,18.77 36.24,19.92 36.43,20.11 37.76,20.11
UG_3V on IN1 (solid shape): 44.74,24.82 44.74,24.12 44.55,23.93 42.75,23.93 42.68,24 42.68,24.84 42.85,25.01 44.55,25.01
UG_5V on TOP (solid shape): 51.46,17.47 51.46,16.01 51.3,15.84 50.4,15.84 50.33,15.9 50.33,17.55 50.4,17.62 51.31,17.62
UG_5V on TOP (solid shape): 50.45,24.22 50.45,23.89 50.26,23.7 49.16,23.7 48.9,23.97 48.9,24.17 47.79,24.17 47.73,24.23 47.73,24.3 47.79,24.36 50.31,24.36
UG_5V on IN1 (solid shape): 51.41,18.09 51.41,15.78 51.3,15.66 50.35,15.66 50.09,15.92 50.09,18.15 50.19,18.25 51.25,18.25
UG_5V on IN1 (solid shape): 51.35,24.34 51.36,24.34 51.36,23.12 51.31,23.07 49.94,23.07 49.01,23.99 49.01,24.37 49.2,24.57 51.12,24.57
N15438178 on TOP (solid shape): 50.27,48 50.27,45.66 49.98,45.37 47.75,45.37 47.44,45.05 47.44,44.14 47.09,43.79 45.34,43.79 44.96,44.17 44.96,47.87 45.34,48.25 50.02,48.25
N17156946 on TOP (solid shape): 72.58,102.04 72.58,99.88 73.6,98.86 73.6,97.78 73.5,97.68 71.24,97.68 71.06,97.85 71.06,100.05 71.44,100.42 71.44,102.1 71.55,102.21 72.41,102.21
N17156946 on BOTTOM (solid shape): 73.27,100.1 73.27,98.61 73.01,98.35 71.91,98.35 71.71,98.56 71.71,100.12 71.81,100.22 73.15,100.22
N17156948 on TOP (solid shape): 70.02,97.14 70.02,95.9 69.89,95.77 68.65,95.77 68.5,95.93 68.5,97.16 68.61,97.27 69.89,97.27
N17639884 on BOTTOM (solid shape): 86.74,104.66 86.74,103.67 86.79,103.62 87.59,103.62 87.66,103.56 87.66,103.01 87.58,102.93 87.55,102.96 87.41,103.03 87.25,103.05 86.78,103.05 86.08,103.75 86.05,103.75 86.03,103.76 85.69,103.76 85.62,103.84 85.62,104.68 85.67,104.73 86.68,104.73
N20711035 on BOTTOM (solid shape): 195.66,64.49 195.66,63.16 195.52,63.02 195.1,63.02 195.02,63.1 195.02,64.61 195.09,64.67 195.48,64.67
N20813044 on BOTTOM (solid shape): 198.69,17.54 198.69,15.75 197.75,14.81 197.75,14.04 197.64,13.92 197.07,13.92 197,13.99 197,15.04 196.99,15.05 196.98,15.05 196.98,17.54 197.14,17.71 198.53,17.71
N20813052 on TOP (solid shape): 198.02,25.05 199.1,25.05 199.36,24.79 199.36,23.25 199.21,23.1 198.31,23.1 198.22,23.02 198.22,21.69 197.68,21.15 197.68,17 197.46,16.78 195.15,16.78 195.01,16.92 195.01,24.49 195.6,25.07 198,25.07
N20813052 on BOTTOM (solid shape): 198.43,24.7 198.43,21.69 198.67,21.45 198.67,18.44 198.39,18.16 197.07,18.16 197.06,18.18 196.69,17.81 196.69,14.8 196.47,14.58 195.42,14.58 195.18,14.82 195.18,21.89 195.4,22.11 196.71,22.11 197.67,23.07 197.67,24.73 197.84,24.91 198.22,24.91
N20813085 on BOTTOM (solid shape): 206.38,17.42 206.38,16.08 206.53,15.93 208.21,15.93 208.32,15.81 208.32,14.85 208.17,14.7 206.75,14.7 206.5,14.94 206.5,15.54 206.33,15.71 205.78,15.71 205.7,15.79 205.7,16.5 205.55,16.65 204.65,16.65 204.38,16.92 204.38,17.44 204.6,17.66 206.14,17.66
N20826302 on BOTTOM (solid shape): 76.77,20.8 76.77,20.49 76.77,20.49 76.77,20.2 76.76,20.18 76.86,20.08 76.88,20.08 77.07,19.89 77.07,18.24 76.99,18.16 76.9,18.16 76.85,18.22 76.85,19.41 76.71,19.55 75.73,19.55 75.59,19.69 75.59,20.21 76.31,20.93 76.63,20.93
N24606174 on TOP (solid shape): 192.22,65.93 192.22,65.32 192.12,65.22 191.66,65.22 191.46,65.01 191.46,64.05 191.3,63.9 190.2,63.9 190.08,64.01 190.08,65.88 190.25,66.04 192.1,66.04
N24606174 on BOTTOM (solid shape): 190.82,66.81 190.82,66.09 191.06,65.85 191.86,65.85 191.98,65.74 191.98,65.42 191.85,65.29 191.33,65.29 190.53,66.09 190.53,66.82 190.58,66.87 190.76,66.87
N48708367 on BOTTOM (solid shape): 74.39,16.75 76.2,16.75 76.25,16.7 76.25,16.59 76.22,16.55 74.77,16.55 74.18,15.97 72.96,15.97 72.86,16.07 72.86,17.45 72.93,17.52 73.62,17.52
N48708425 on BOTTOM (solid shape): 73.94,20.96 73.94,18.61 74.98,17.57 76.22,17.57 76.25,17.53 76.25,17.39 76.22,17.35 74.6,17.35 73.71,18.24 73.71,20.35 73.57,20.49 72.95,20.49 72.9,20.54 72.9,20.98 73,21.09 73.81,21.09
N49522072 on TOP (solid shape): 53.07,41.48 53.07,40.29 52.14,39.36 52.14,39.3 51.23,38.39 51.21,38.39 50.86,38.21 50.68,37.86 50.68,37.85 50.51,37.68 50.51,37.43 50.47,37.42 50.19,37.07 50.47,36.73 50.51,36.72 50.51,36.51 50.71,36.31 52.09,36.31 52.48,35.91 52.48,35.07 52.25,34.84 49.6,34.84 49.38,35.06 49.3,35.35 49.18,35.65 49.18,37.99 49.22,38 49.49,38.23 49.41,38.58 49.38,38.62 50.65,39.88 50.65,41.32 50.85,41.52 53.03,41.52
N78967043 on TOP (solid shape): 9.25,25.31 9.25,24.5 9.02,24.27 8.46,24.27 8.02,24.72 7.27,24.72 7.11,24.87 7.11,25.43 7.39,25.71 8.85,25.71
N80905978 on BOTTOM (solid shape): 194.2,80 194.2,78.22 193.53,77.55 192.2,77.55 192.17,77.59 192.17,80 192.47,80.31 193.89,80.31
N80906026 on BOTTOM (solid shape): 191.87,87.68 193.18,87.68 193.25,87.62 193.25,86.08 193.23,86.07 193.44,85.87 195.28,85.87 195.38,85.77 195.38,83.63 195.24,83.49 194.86,83.49 194.74,83.61 194.74,85.32 194.5,85.56 192.78,85.56 192.61,85.73 192.61,86.92 192.62,86.93 192.46,87.1 191.8,87.1 191.71,87.19 191.71,87.58 191.82,87.7 191.86,87.7

Small or netless copper shapes (teardrops, artwork), in the pictures only: 25 on TOP, 405 on BOTTOM, 1 on IN2

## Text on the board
Ref Des/Silkscreen Bottom: DDR3L | DIMM A | LOW VOLTAGE | DIMM B | Rev:A00 | PWB:MJ0P2 | ALL RIGHT RESERVED | COPYRIGHT 2014 | LED | BT | WLAN | WIGIG | HCA | WWAN
User.Comments: {\Fgdt;n}\Ftxt;3.18 | LA-A961P | 2015-09-10 | 2014-09-10 | Minjia_Cai | ZBU10 | charger | 3v& 5v | +1.8V | +1.05v
Ref Des/Silkscreen Top: M2.5X5L | H19 | H18
BODY_CENTER: trace Width | LAYER | NAME | 39 ohm | 5.2mil | 50 ohm | 3.3mil | 4.8mil | 4mil | Single 52ohm | Width/space | 4.5 / 3.2 | 85 ohm | Single 50ohm | 4 / 4.5 | Single 48ohm | 3.6 / 3.2 | 3.3 / 3.5 | 90 ohm | 4 / 6.5 | 4 / 6 | 3.3 / 11.7 | 100 ohm | 3.5 / 9 | 9.5 / 5 | 11 / 5 | No Refer | Refer | L1-TOP | L2-GND1 | L3-IN1 | L4-GND2 | L4-IN2 | L5-IN3 | L7-VCC | L8-IN4 | L9-GND3 | L10-BOT | STACKUP: 10 LAYER | THICKNESS=1.0mm
USER_PART_NUM_BOTTOM: FIGURE | SIZE | 7.0 | 8.0 | 10.0 | 20.0 | 28.0 | 35.0 | 39.0 | 47.0 | 110.0 | 122.0 | 130.0 | 150.0 | 37.0 | 40.0 | 43.0 | 63.0 | 71.0 | 83.0 | 39.0x28.0 | 39.0x33.0 | 69.0x28.0 | 71.0x31.0 | 79.0x31.0 | 87.0x31.0 | 94.0x28.0 | 102.0x28.0 | 102.0x83.0 | 110.0x39.0 | 118.0x30.0 | 55.0x43.0 | DRILL CHART: TOP to BOTTOM | ALL UNITS ARE IN MILS | TOLERANCE | +3.0/-3.0 | +2.0/-2.0 | PLATED | NON-PLATED | QTY | 72 | 5259 | 179 | 29 | 18 | 10 | 9 | 13 | 2 | 4 | 5 | 1 | 6
User.21: GND4
User.22: +PWR_SRC | +5V_ALW | +5V_USB_CHG_PWR | +3.3V_ALW | +3.3V_RUN | GND | +VCC_CORE | +BATT_SUM | +1.05V_RUN | +1.05V_M | CHAGER_SRC | +DOCK_PWR_BAR | +3V_ALW
